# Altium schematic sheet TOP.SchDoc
size A3; Revision: V1.2; SheetNumber: 1; SheetTotal: 10
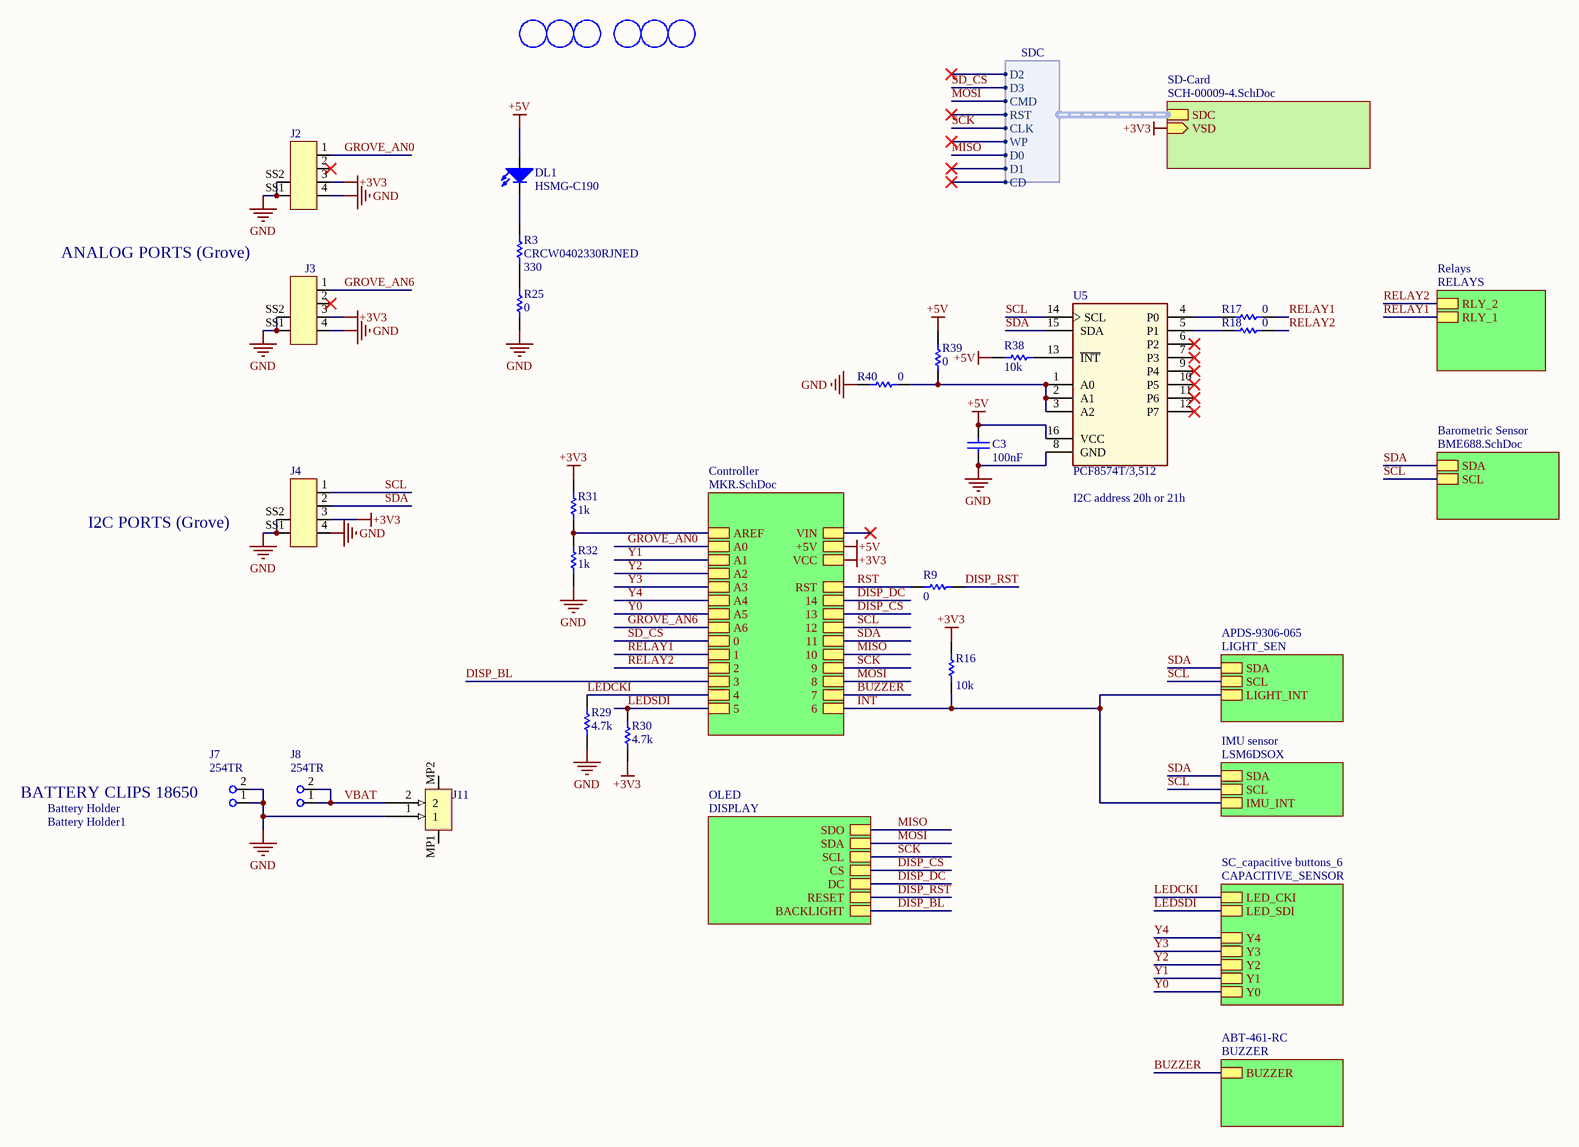
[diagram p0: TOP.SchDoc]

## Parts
Battery_Holder1  Battery Holder  [Battery Holder-Footprint-1]  (no BOM)
C3  value 100nF  [CAP-0402]  (hidden comment: GRM155R61H104KE19D)
DL1  HSMG-C190  [LEDC1608X80N-AK]
FD1  Fiducial mark 1.5mm  [FIDUCIAL-1.5]  (value not drawn)  (no BOM)
FD2  Fiducial mark 1.5mm  [FIDUCIAL-1.5]  (value not drawn)  (no BOM)
FD3  Fiducial mark 1.5mm  [FIDUCIAL-1.5]  (value not drawn)  (no BOM)
FD4  Fiducial mark 1.5mm  [FIDUCIAL-1.5]  (value not drawn)  (no BOM)
FD5  Fiducial mark 1.5mm  [FIDUCIAL-1.5]  (value not drawn)  (no BOM)
FD6  Fiducial mark 1.5mm  [FIDUCIAL-1.5]  (value not drawn)  (no BOM)
J2  320110032  [320110032-Footprint-1]  (value not drawn)
J3  320110032  [320110032-Footprint-1]  (value not drawn)
J4  320110032  [320110032-Footprint-1]  (value not drawn)
J7  254TR  [254TR-Footprint-1]
J8  254TR  [254TR-Footprint-1]
J11  B2B-PH-SM4-TB(LF)(SN)  [New footprint 1]  (value not drawn)
R3  CRCW0402330RJNED  value 330  [RES-0402]
R9  value 0  [RES-0402]  (hidden comment: CRCW04020000Z0EDC)
R16  value 10k  [RES-0402]  (hidden comment: CRCW040210K0FKED)
R17  value 0  [RES-0402]  (hidden comment: CRCW04020000Z0EDC)
R18  value 0  [RES-0402]  (hidden comment: CRCW04020000Z0EDC)
R25  value 0  [RES-0402]  (hidden comment: CRCW04020000Z0EDC)
R29  value 4.7k  [RES-0402]  (hidden comment: RC0402FR-074K7L)
R30  value 4.7k  [RES-0402]  (hidden comment: RC0402FR-074K7L)
R31  value 1k  [RES-0402]  (hidden comment: CRCW04021K00FKEDC)
R32  value 1k  [RES-0402]  (hidden comment: CRCW04021K00FKEDC)
R38  value 10k  [RES-0402]  (hidden comment: CRCW040210K0FKED)
R39  value 0  [RES-0402]  (hidden comment: CRCW04020000Z0EDC)
R40  value 0  [RES-0402]  (hidden comment: CRCW04020000Z0EDC)
U5  PCF8574T/3,512  [SOIC127P1030X265-16N]

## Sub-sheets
ABT-461-RC = BUZZER: BUZZER
APDS-9306-065 = LIGHT_SEN: SCL, SDA, LIGHT_INT
Barometric Sensor = BME688.SchDoc: SDA, SCL
Controller = MKR.SchDoc: 10, 8, 11, 1, A2, 0, RST, 5, A5, 12, 7, A3, 4, 2, A4, 14, A6, 9, 6, 3, 13, AREF, VIN, +5V, VCC, A1, A0
IMU sensor = LSM6DSOX: SDA, SCL, IMU_INT
OLED = DISPLAY: RESET, SCL, BACKLIGHT, SDA, SDO, DC, CS
Relays = RELAYS: RLY_2, RLY_1
SC_capacitive buttons_6 = CAPACITIVE_SENSOR: Y3, Y2, Y4, Y1, Y0, LED_CKI, LED_SDI
SD-Card = SCH-00009-4.SchDoc: SDC (harness SDC), VSD (in)

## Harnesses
SDC: CD, CLK, CMD, D0, D1, D2, D3, RST, WP

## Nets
+3V3: J2.3 J3.3 J4.3 R16.2 R30.1 R31.2 ; sheet SD-Card/VSD, sheet Controller/VCC
+5V: C3.2 DL1.A R38.2 R39.2 U5.16(VCC) ; sheet Controller/+5V
GND: C3.1 J2.4 J2.SS1 J2.SS2 J3.4 J3.SS1 J3.SS2 J4.4 J4.SS1 J4.SS2 J7.1(-) J7.2(GND) J11.1 R25.1 R29.1 R32.1 R40.1 U5.8(GND)
BUZZER: sheet ABT-461-RC/BUZZER, sheet Controller/7
DISP_BL: sheet OLED/BACKLIGHT, sheet Controller/3
DISP_CS: sheet OLED/CS, sheet Controller/13
DISP_DC: sheet OLED/DC, sheet Controller/14
DISP_RST: R9.1 ; sheet OLED/RESET
GROVE_AN0: J2.1 ; sheet Controller/A0
GROVE_AN6: J3.1 ; sheet Controller/A6
INT: R16.1 ; sheet IMU sensor/IMU_INT, sheet APDS-9306-065/LIGHT_INT, sheet Controller/6
LEDCKI: R29.2 ; sheet SC_capacitive buttons_6/LED_CKI, sheet Controller/4
LEDSDI: R30.2 ; sheet SC_capacitive buttons_6/LED_SDI, sheet Controller/5
MISO: sheet OLED/SDO, sheet Controller/10, sheet SD-Card/SDC.D0
MOSI: sheet OLED/SDA, sheet Controller/8, sheet SD-Card/SDC.CMD
RELAY1: R17.2 ; sheet Relays/RLY_1, sheet Controller/1
RELAY2: R18.2 ; sheet Relays/RLY_2, sheet Controller/2
RST: R9.2 ; sheet Controller/RST
SCK: sheet OLED/SCL, sheet Controller/9, sheet SD-Card/SDC.CLK
SCL: J4.1 U5.14(SCL) ; sheet Barometric Sensor/SCL, sheet IMU sensor/SCL, sheet APDS-9306-065/SCL, sheet Controller/12
SD_CS: sheet Controller/0, sheet SD-Card/SDC.D3
SDA: J4.2 U5.15(SDA) ; sheet Barometric Sensor/SDA, sheet IMU sensor/SDA, sheet APDS-9306-065/SDA, sheet Controller/11
VBAT: J8.1(-) J8.2(GND) J11.2
Y0: sheet SC_capacitive buttons_6/Y0, sheet Controller/A5
Y1: sheet SC_capacitive buttons_6/Y1, sheet Controller/A1
Y2: sheet SC_capacitive buttons_6/Y2, sheet Controller/A2
Y3: sheet SC_capacitive buttons_6/Y3, sheet Controller/A3
Y4: sheet SC_capacitive buttons_6/Y4, sheet Controller/A4
NetDL1_C: DL1.C R3.2
NetR3_1: R3.1 R25.2
NetR17_1: R17.1 U5.4(P0)
NetR18_1: R18.1 U5.5(P1)
NetR31_1: R31.1 R32.2 ; sheet Controller/AREF
NetR38_1: R38.1 U5.13(~{INT})
NetR39_1: R39.1 R40.2 U5.1(A0) U5.2(A1) U5.3(A2)

Not connected (* = marked no-connect by the designer): J2 2*; J3 2*; J11 MP1 MP2; U5 6(P2)* 7(P3)* 9(P4)* 10(P5)* 11(P6)* 12(P7)*

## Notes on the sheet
- ANALOG PORTS (Grove)
- I2C PORTS (Grove)
- (near U5) I2C address 20h or 21h
- (near Battery_Holder1) BATTERY CLIPS 18650

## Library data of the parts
Battery_Holder1 = UT0019-A.1: Battery holder marker
C3 = C0015-A.11: CAP CHIP 0402 100nF 50V X5R 10%; Manufacturer: Murata; Code Arduino: A5141
DL1 = L0009-A.4: LED SMD 0603 GREEN/568 15mcd 120^; Manufacturer: Broadcom; Code Arduino: 2204
FD1-FD6 = UT0000-A.3
J2-J4 = J0274-A.1: CONN GROVE SMD-90D(4+2P-2.0) 320110032; Manufacturer: Seeed; Code Arduino: A5410
J7 J8 = J0053-A.6: CONN BATTERY HOLDER 18650 CLIP SMT; Manufacturer: Keystone Electronics; Code Arduino: J0053
J11 = J0103-A.2: CONN HEADER SMD 2 POS 0.079" (2.00mm); Manufacturer: JST; Code Arduino: J0103
R3 = R0017-A.11: RES CHIP 0402 330R 5% 1/16W; Manufacturer: Vishay; Power: 63mW; Code Arduino: 2229
R9 R17 R18 R25 R39 R40 = R0000-A.11: RES CHIP 0402 0R 1/16W; Manufacturer: Vishay; Code Arduino: 0039; Power: 63mW; Tolerance: J
R16 R38 = R0003-A.11: RES CHIP 0402 10K 1% 1/16W; Manufacturer: Vishay; Code Arduino: 0136; Power: 63mW
R29 R30 = R0013-A.11: RES CHIP 0402 4K7 1% 1/16W; Manufacturer: Yageo; Code Arduino: 2196; Power: 63mW
R31 R32 = R0007-A.11: RES CHIP 0402 1K 1% 1/16W; Manufacturer: Vishay; Code Arduino: 0140; Power: 63mW
U5 = U0249-A.2: IC EXTENDED I/O EXPANDER I2C 8-bit; Manufacturer: NXP; Max Supply Voltage: 6V; Min Supply Voltage: 2.5V; Code Arduino: U0249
